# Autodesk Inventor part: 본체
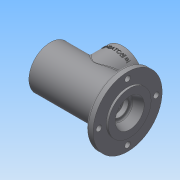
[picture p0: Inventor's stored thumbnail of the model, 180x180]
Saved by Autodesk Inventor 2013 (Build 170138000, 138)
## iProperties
Created: 2016-08
Part Number: 본체
Material: 일반
Document SubType Name: Modeling
Designer: Administrator
Density: 1 g/cm^3
Author: Administrator
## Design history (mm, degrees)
sketch "스케치1"
  geometry: L1 (-57.5, 0)-(57.5, 0); L2 (-57.5, 31)-(44.5, 31); L3 (44.5, 31)-(44.5, 50); L4 (44.5, 50)-(54.5, 50); L5 (57.5, 0)-(57.5, 21); L6 (57.5, 31)-(54.5, 31); L7 (54.5, 31)-(54.5, 50); L8 (-57.5, 21)-(-48.5, 21); L9 (-48.5, 21)-(-48.5, 24); L10 (-48.5, 24)-(-45.5, 24); L11 (-45.5, 24)-(-45.5, 20); L12 (-45.5, 20)-(-36.5, 20); L13 (-36.5, 20)-(-36.5, 17.5); L14 (-36.5, 17.5)-(-33.25, 17.5); L15 (-33.25, 17.5)-(-33.25, 18.5); L16 (-33.25, 18.5)-(-31.5, 18.5); L17 (-31.5, 18.5)-(-31.5, 17.5); L18 (-31.5, 17.5)-(-20.5, 17.5); L19 (17.5, 17.5)-(28.5, 17.5); L20 (28.5, 17.5)-(28.5, 16.5); L21 (28.5, 16.5)-(33.5, 16.5); L22 (33.5, 16.5)-(33.5, 10); L23 (33.5, 10)-(36.2, 10); L24 (36.2, 10)-(36.2, 12.5); L25 (36.2, 12.5)-(43.5, 12.5); L26 (43.5, 12.5)-(43.5, 16); L27 (43.5, 16)-(57.5, 21); L28 (-57.5, 31)-(-57.5, 21); L29 (57.5, 21)-(57.5, 31); L30 (-57.5, 21)-(-57.5, 0); L31 (17.5, 17.5)-(17.5, 24); L32 (17.5, 24)-(-20.5, 24); L33 (-20.5, 24)-(-20.5, 17.5); 2 further points
  constraints: 66 end point, 9 parallel, 9 perpendicular, 2 coincident, 1 horizontal, 1 midpoint
  dimensions: "d0" = 115 distance of L1.start L1.end; "d1" = 31 distance of L1.start L2.start; "d2" = 102 distance of L2.start L2.end; "d4" = 10 distance of L3.end L4.end; "d5" = 31 distance of L1.end L6.start; "d6" = 3 distance of L6.start L6.end; "d7" = 100 diameter of L4 L1; "d13" = 9 distance of L8.start L8.end; "d14" = 3 distance of L9.end L10.end; "d15" = 9 distance of L11.end L12.end; "d18" = 21 distance of L1.end L5.end; "d19" = 14 horizontal distance of L1.end L26.end; "d20" = 16 vertical distance of L1.end L26.end; "d21" = 10 horizontal distance of L22.end L25.end; "d22" = 2.7 distance between parallel lines of L24 L22; "d24" = 5 distance of L20.end L21.end; "d25" = 60 distance of L17.end L19.end; "d27" = 1.75 distance between parallel lines of L17 L15; "d28" = 42 diameter of L8 L1; "d29" = 48 diameter of L10 L1; "d30" = 40 diameter of L12 L1; "d31" = 35 diameter of L14 L1; "d32" = 37 diameter of L16 L1; "d33" = 35 diameter of L18 L1; "d34" = 35 diameter of L19 L1; "d35" = 33 diameter of L21 L1; "d36" = 20 diameter of L23 L1; "d37" = 25 diameter of L25 L1; "d38" = 1 distance of L16.end L17.end; "d92" = 38 distance of L31.end L32.end; "d93" = 11 distance from line of L32.end L17; "d97" = 24 distance from line of point (0, 0) L32
revolve "회전1" sketch "스케치1" stored, may be unused: angle "d41" = 90 deg
feature "스레드1" dims "d42" = 10, "d43" = 0
fillet "모깎기2" dims "d45" = 3
chamfer "모따기1" distance "d46" = 0.7; stored, may be unused: second distance "d47" = 2, angle "d48" = 30 deg
fillet "모깎기3" dims "d49" = 3
fillet "모깎기4" dims "d50" = 0.3
sketch "스케치3"
  geometry: C1 r 31 at (0, 0) reference; C2 r 50 at (0, 0) reference; A1 r 41.5 centre (0, 0) between (0, 41.5) and (-41.5, 0); 2 further points
  constraints: 4 point on circle, 2 horizontal alignment, 2 vertical alignment, 1 centre point, 1 coincident
  dimensions: "d51" = 83 diameter of A1
hole "구멍1" sketch "스케치3" at (0, 41.5), (-41.5, 0), (0, -41.5), (41.5, 0) diameter "d52" = 8; stored, may be unused: countersink angle "d56" = 90 deg, drill point angle "d58" = 118 deg; dims "d53" = 6, "d54" = 4, "d55" = 2, "d57" = 8
node "작업 평면1"
sketch "스케치4"
  geometry: L1 (57.5, 31)-(57.5, -31) reference; C1 r 30 at (1.5, 0); C2 r 19 at (1.5, 0); 1 further point
  constraints: 2 centre point, 1 coincident
  dimensions: "d60" = 60 diameter of C1; "d61" = 38 diameter of C2; "d62" = 56 distance from line of C1.centre L1; "d63" = 0 vertical distance of point (0, 0) C1.centre
fillet "모깎기10" dims "d98" = 3
extrude "돌출1" join sketch "스케치4" stored distance "d64" = 10; taper "d65" = 0 deg
extrude "돌출2" cut sketch "스케치4" distance "d66" = 50; taper "d67" = 0 deg
sketch "스케치5"
  geometry: C1 r 19 at (0, 0) reference; C2 r 30 at (0, 0) reference; A1 r 24 centre (0, 0) between (0, 24) and (-24, 0); 3 further points
  constraints: 4 point on circle, 2 horizontal alignment, 2 vertical alignment, 1 centre point, 1 coincident
  dimensions: "d68" = 48 diameter of A1
hole "구멍2" sketch "스케치5" at (0, 24), (-24, 0), (0, -24), (24, 0) diameter "d69" = 3.242; stored, may be unused: countersink angle "d73" = 90 deg, drill point angle "d75" = 118 deg; dims "d70" = 8, "d71" = 4, "d72" = 2, "d74" = 10
fillet "모깎기5" dims "d76" = 0.3
fillet "모깎기6" dims "d77" = 3
chamfer "모따기2" distance "d78" = 1; stored, may be unused: second distance "d79" = 2, angle "d80" = 30 deg
chamfer "모따기3" distance "d81" = 1; stored, may be unused: second distance "d82" = 2, angle "d83" = 30 deg
node "작업 평면2"
sketch "스케치7"
  geometry: L1 (-31.5, 49)-(28.5, 49) reference; L2 (-57.5, -31)-(-57.5, 31) reference; 2 further points
  constraints: 1 other
  dimensions: "d88" = 10 distance from line of point (-1.5, 39) L1; "d89" = 56 distance from line of L2 point (-1.5, 39)
feature "엠보싱1" sketch "스케치7" dims "d19" = 14, "d90" = 0.5, "d91" = 0
fillet "모깎기8" dims "d95" = 3
fillet "모깎기9" dims "d96" = 3
node "솔리드1"
other parameters: "d59" = 49, "d87" = 30.5
